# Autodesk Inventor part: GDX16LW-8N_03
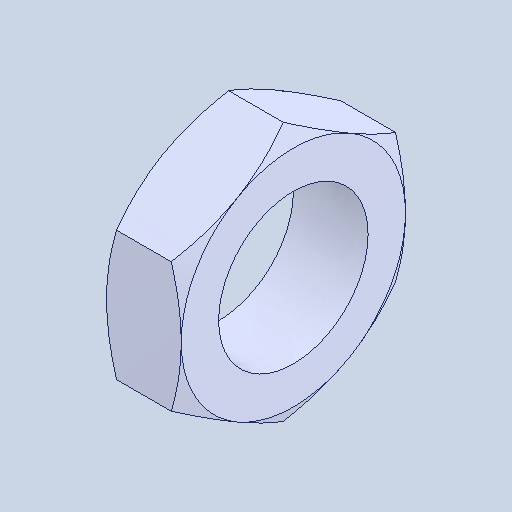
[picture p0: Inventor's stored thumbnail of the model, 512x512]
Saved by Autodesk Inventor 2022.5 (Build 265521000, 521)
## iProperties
Created: 2024-06
Part Number: GDX16LW-8N_03
Material: 一般
Document SubType Name: Modeling
Designer: ImaoCorp
Density: 1 g/cm^3
Appearance: 既定
Author: ImaoCorp
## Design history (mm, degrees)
feature "GDX16LW-8N_03"
node "ソリッド1"
